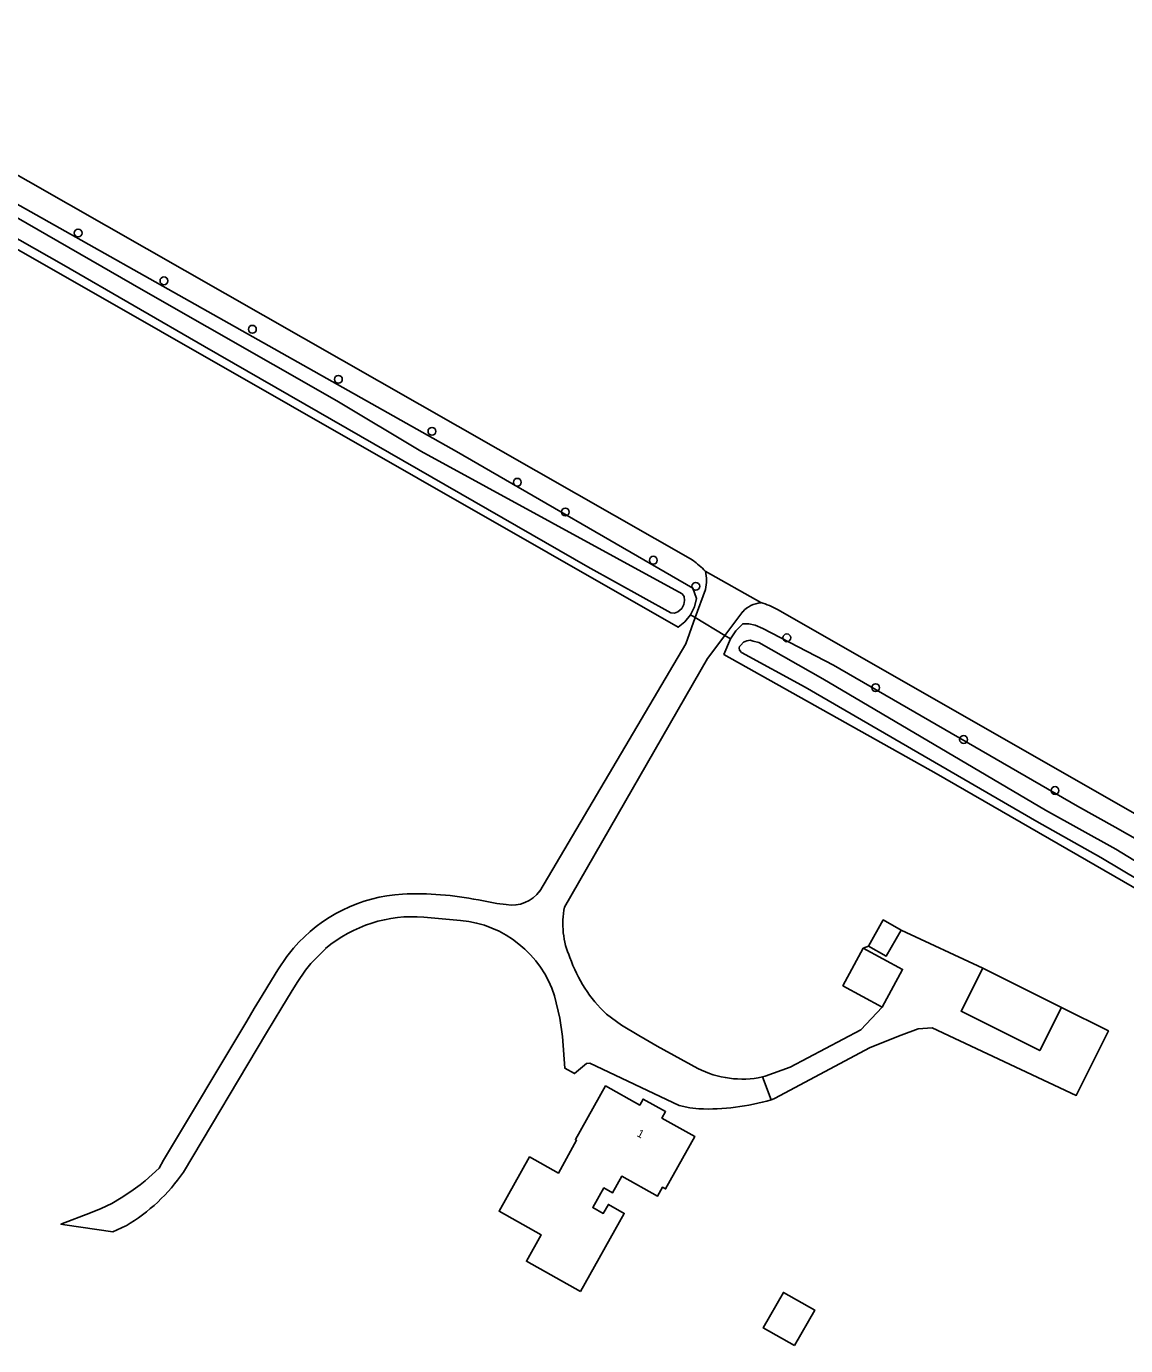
# Model space of a CAD drawing. Extents: x 156502 to 159074, y 384229 to 386094.
# Drawn here: x 158859.3 to 158996.7, y 384967.5 to 385132.3 of the extents above; entities that cross this region are included whole.
import ezdxf

# ---------------------------------------------------------------- set-up
doc = ezdxf.new("R2010")
doc.units = 0
for name, color, linetype in [('IMGEO_Boom', 7, 'Continuous'), ('IMGEO_Gemengd_bos', 7, 'Continuous'), ('IMGEO_Groenvoorziening', 7, 'Continuous'), ('IMGEO_Inrit_gesloten', 7, 'Continuous'), ('IMGEO_Pand', 7, 'Continuous'), ('IMGEO_Pand_nummerreeks', 7, 'Continuous'), ('IMGEO_Rijbaan_lokaal_gesloten', 7, 'Continuous'), ('IMGEO_Waterloop', 7, 'Continuous')]:
    doc.layers.add(name, color=color, linetype=linetype)

msp = doc.modelspace()

# ---------------------------------------------------------------- linework, layer by layer
at = {"layer": 'IMGEO_Boom'}
for centre in [(158865.8, 385106.48), (158876.52, 385100.51), (158887.58, 385094.46), (158898.33, 385088.21), (158910.02, 385081.71), (158920.69, 385075.35), (158926.7, 385071.63), (158937.7, 385065.61), (158943, 385062.35), (158954.38, 385055.92), (158965.49, 385049.69), (158976.47, 385043.21), (158987.9, 385036.84)]:
    msp.add_circle(centre, 0.489, dxfattribs=at)
at = {"layer": 'IMGEO_Gemengd_bos'}
for points in [[(158587.52, 385259.81), (158603.48, 385250), (158662.11, 385216.13), (158774.28, 385152.08), (158859.86, 385103.52), (158940.81, 385057.23), (158941.64, 385057.92), (158942.32, 385058.77)], [(158942.32, 385058.77), (158942.94, 385058.44)], [(158946.64, 385056.22), (158947.34, 385055.8)], [(158947.34, 385055.8), (158946.52, 385053.84), (158973.04, 385038.98), (159000, 385023.43), (159029.69, 385006.3), (159042.56, 384998.73), (159042.95, 384998.18), (159042.89, 384997.7)]]:
    msp.add_lwpolyline(points, dxfattribs=at)
at = {"layer": 'IMGEO_Groenvoorziening'}
for points in [[(158829.41, 385126.26), (158913.09, 385079.19), (158942.62, 385062.12), (158943.1, 385060.85), (158942.82, 385059.77), (158942.32, 385058.77)], [(158947.34, 385055.8), (158948.02, 385056.81), (158948.87, 385057.68), (158949.63, 385057.66), (158950.42, 385057.5), (158951.36, 385057.1), (158960.21, 385052.52), (158990.71, 385034.88), (158995.43, 385032.25), (159017.37, 385019.83), (159025.98, 385014.98), (159034.31, 385009.93), (159037.58, 385007.93), (159045.89, 385002.24), (159047.29, 385001.16), (159047.74, 385000.4), (159048, 384999.41), (159047.98, 384998.33), (159047.77, 384997.15), (159047.38, 384996.31), (159046.6, 384995.5)]]:
    msp.add_lwpolyline(points, dxfattribs=at)
at = {"layer": 'IMGEO_Inrit_gesloten'}
for points in [[(158942.94, 385058.44), (158944.2, 385061.97)], [(158942.94, 385058.44), (158941.77, 385055.15), (158923.51, 385024.29)], [(158946.64, 385056.22), (158942.94, 385058.44)], [(158948.88, 385059.19), (158946.64, 385056.22)], [(158926.59, 385022.28), (158944.46, 385053.32), (158946.64, 385056.22)], [(158919.31, 385022.59), (158918.14, 385022.73), (158916.45, 385023.07), (158915.82, 385023.18)], [(158909.01, 385021.04), (158913.61, 385020.61)], [(158892.72, 385017.16), (158891.9, 385016.1), (158890.77, 385014.46), (158889.95, 385013.16), (158888.78, 385011.23), (158887.82, 385009.63), (158886.88, 385008.05), (158876.48, 384990.67), (158875.93, 384989.68), (158874.19, 384988.07), (158873.55, 384987.59), (158872.38, 384986.74), (158871.19, 384985.95), (158870.02, 384985.27), (158868.68, 384984.62), (158867.35, 384984.08), (158863.65, 384982.67), (158864.12, 384982.6), (158870.15, 384981.73), (158871.78, 384982.48)], [(158878.96, 384989.18), (158889.36, 385006.57), (158890.3, 385008.15), (158891.25, 385009.74), (158892.41, 385011.64), (158893.19, 385012.88), (158894.23, 385014.4), (158894.9, 385015.25), (158896.74, 385017.12)], [(158925.36, 385011.19), (158926, 385008.42), (158926.33, 385006.1), (158926.65, 385002.15), (158927.84, 385001.49), (158929.36, 385002.73), (158929.75, 385002.79), (158940.91, 384997.5), (158942.27, 384997.21), (158943.4, 384997.08)], [(158943.26, 385002.12), (158938.16, 385004.92), (158936.68, 385005.79), (158935.89, 385006.25), (158933.7, 385007.54), (158931.82, 385008.91)]]:
    msp.add_lwpolyline(points, dxfattribs=at)
for centre, radius, start, end in [((158940.1, 385063.09), 4.25, 344.726, 15.6285), ((158951.51, 385056.73), 3.6, 96.2011, 137.0107), ((158907.54, 385004.39), 19.56, 93.4931, 139.2461), ((158908.01, 384983.39), 40.55, 78.8958, 92.354), ((158920.02, 385026.85), 4.32, 260.5126, 323.7758), ((158936.67, 385020.18), 10.29, 168.1979, 204.0633), ((158907.71, 385003.94), 17.15, 85.6652, 129.7815), ((158912.33, 385006.99), 13.69, 17.8898, 84.6361), ((158944.09, 385021.81), 17.8, 199.1202, 226.442), ((158948.81, 385013.16), 12.36, 243.3157, 281.7529), ((158944.47, 385025.09), 28.03, 267.8223, 286.4497), ((158860.5, 385001.75), 22.33, 300.3479, 325.767)]:
    msp.add_arc(centre, radius, start, end, dxfattribs=at)
at = {"layer": 'IMGEO_Pand'}
for points in [[(158968.65, 385019.42), (158966.42, 385020.68), (158964.58, 385017.42)], [(158964.58, 385017.42), (158966.8, 385016.16), (158968.65, 385019.42)], [(158963.93, 385017.16), (158961.38, 385012.45), (158966.31, 385009.79)], [(158966.31, 385009.79), (158968.85, 385014.5), (158963.93, 385017.16)], [(158978.86, 385014.67), (158976.16, 385009.28), (158986, 385004.36), (158988.7, 385009.75)], [(158988.7, 385009.75), (158978.86, 385014.67)], [(158928.58, 384974.25), (158934.06, 384984.02), (158932.07, 384985.14), (158931.44, 384984.02), (158930.13, 384984.75), (158931.51, 384987.21), (158932.59, 384986.61), (158933.75, 384988.67), (158938.21, 384986.17), (158938.83, 384987.29), (158939.22, 384987.07), (158942.89, 384993.62), (158938.76, 384995.93), (158939.22, 384996.74), (158936.42, 384998.31), (158936, 384997.55), (158931.72, 384999.95), (158927.96, 384993.24), (158928.11, 384993.16), (158925.82, 384989.06), (158922.22, 384991.08), (158918.42, 384984.29), (158923.68, 384981.34), (158921.82, 384978.04), (158928.58, 384974.25)], [(158955.35, 384967.51), (158957.86, 384971.94), (158953.95, 384974.16), (158951.43, 384969.72), (158955.35, 384967.51)]]:
    msp.add_lwpolyline(points, dxfattribs=at)
at = {"layer": 'IMGEO_Rijbaan_lokaal_gesloten'}
for points in [[(158831.21, 385129.16), (158854.77, 385115.68), (158942.61, 385065.61)], [(158944.19, 385064.23), (158951.12, 385060.31)], [(158953.23, 385059.44), (159049.23, 385004.63), (159050.75, 385003.85), (159058.37, 384999.6), (159059.88, 384998.7)], [(158978.86, 385014.67), (158968.65, 385019.42)], [(158964.58, 385017.42), (158963.93, 385017.16)], [(158966.31, 385009.79), (158963.63, 385006.95), (158954.8, 385002.27), (158951.66, 385001.18), (158951.33, 385001.06)], [(158952.41, 384998.21), (158952.76, 384998.34), (158952.83, 384998.37), (158964.81, 385004.73), (158968.65, 385006.29), (158970.8, 385007.08), (158972.56, 385007.19), (158990.55, 384998.75), (158991.89, 385001.41), (158994.58, 385006.81), (158988.7, 385009.75)], [(158952.41, 384998.21), (158951.33, 385001.06)]]:
    msp.add_lwpolyline(points, dxfattribs=at)
for centre, radius, start, end in [((158936.75, 385057.28), 10.18, 43.0435, 54.8774), ((158948.75, 385051.59), 9.04, 60.2728, 74.8035)]:
    msp.add_arc(centre, radius, start, end, dxfattribs=at)
at = {"layer": 'IMGEO_Waterloop'}
for points in [[(158616.11, 385244.35), (158639.09, 385230.84), (158655.82, 385220.95), (158701.63, 385195.46), (158738.15, 385174.34), (158786.76, 385146.35), (158812.7, 385131.58), (158827.9, 385122.97), (158864.02, 385102.45), (158881.59, 385092.31), (158929.52, 385064.8), (158939.86, 385059.04)], [(158939.86, 385059.04), (158940.34, 385059), (158940.77, 385059.15), (158941.25, 385059.57), (158941.5, 385060.1), (158941.6, 385060.57), (158941.53, 385061.08), (158941.3, 385061.41), (158908.63, 385079.24), (158898.14, 385085.51), (158873.98, 385099.3), (158848.67, 385113.84), (158840.55, 385118.37), (158823.23, 385127.94), (158805.24, 385138.42), (158787.22, 385148.24), (158765.55, 385160.78), (158735.79, 385177.77), (158701.94, 385197.26), (158686.94, 385205.57), (158672.6, 385213.76), (158647.3, 385228.18), (158619.92, 385243.9)], [(159016.57, 385016.65), (158995.51, 385029.52), (158986.7, 385034.41), (158958.87, 385050.8), (158950.87, 385055.35), (158950.18, 385055.52), (158949.8, 385055.61), (158949.4, 385055.55), (158948.98, 385055.36), (158948.63, 385055.01), (158948.48, 385054.85), (158948.43, 385054.65), (158948.48, 385054.37), (158948.71, 385054.1), (158956.65, 385049.75), (158985.61, 385032.98), (158993.61, 385028.49), (159005.69, 385021.28)]]:
    msp.add_lwpolyline(points, dxfattribs=at)

# ---------------------------------------------------------------- texts
at = {"layer": 'IMGEO_Pand_nummerreeks'}
msp.add_text('1', height=1, rotation=332.2785, dxfattribs=at).set_placement((158935.55, 384993.7))

doc.saveas('drawing.dxf')
